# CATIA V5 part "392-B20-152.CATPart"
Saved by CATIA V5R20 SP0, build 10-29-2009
Part number: 392-B20-152
Definition: NONE
Nomenclature: 392-B20-152
Source: Unknown
Description: 392-B20-152
Bounding box of the stored display mesh (mm): x 0 to 152, y -9.274 to 9.274, z -9.2 to 9.2
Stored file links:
  C:\Users\Utente\Desktop\IO LAVORO\3D X SITO CF\X SITO\3D files 392B\392-B20-152.CATPart
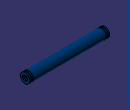
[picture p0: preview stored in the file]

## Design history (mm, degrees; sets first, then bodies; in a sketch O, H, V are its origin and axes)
Body1 "392-B20-152" (main body)
  Solid1: solid without history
